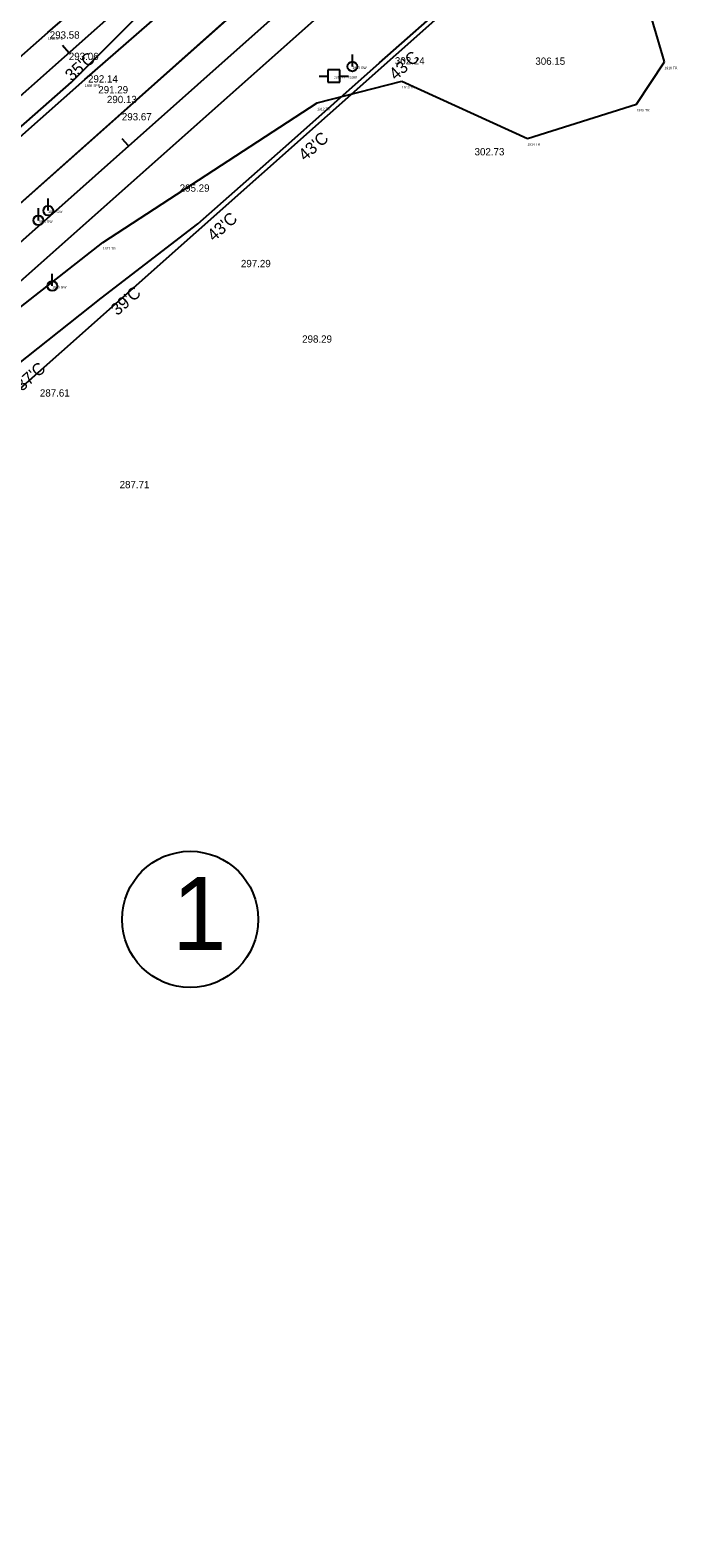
# Model space of a CAD drawing. Extents: x 49683 to 58852, y 49525 to 54803.
# Drawn here: x 55967 to 56233, y 53128 to 53749 of the extents above; entities that cross this region are included whole.
import ezdxf

# ---------------------------------------------------------------- set-up
doc = ezdxf.new("R2010")
doc.units = 0
for name, color, linetype in [('Level 1', 7, 'Continuous'), ('Level 11', 7, 'Continuous'), ('Level 13', 7, 'Continuous'), ('Level 18', 7, 'Continuous'), ('Level 19', 7, 'Continuous'), ('Level 20', 7, 'Continuous'), ('Level 25', 7, 'Continuous'), ('Level 3', 7, 'Continuous'), ('Level 32', 7, 'Continuous'), ('Level 33', 7, 'Continuous'), ('Level 48', 7, 'Continuous'), ('Level 53', 7, 'Continuous'), ('Level 59', 7, 'Continuous'), ('Level 61', 7, 'Continuous'), ('Level 9', 7, 'Continuous')]:
    doc.layers.add(name, color=color, linetype=linetype)

# ---------------------------------------------------------------- blocks, each defined once
blk = doc.blocks.new('GW')
at = {"layer": 'Level 9'}
blk.add_line((0, 0), (0, 5), dxfattribs=at)
blk.add_circle((0, 0), 2, dxfattribs=at)
blk = doc.blocks.new('PP')
at = {"layer": 'Level 9'}
for p, q in [((2.53, 2.45), (-2.47, 2.45)), ((-2.47, 2.45), (-2.47, -2.55)), ((2.53, -2.55), (2.53, 2.45)), ((-5.91, -0.11), (-2.44, -0.11)), ((-2.47, -2.55), (2.53, -2.55)), ((2.45, -0.11), (6.09, -0.11))]:
    blk.add_line(p, q, dxfattribs=at)

msp = doc.modelspace()

# ---------------------------------------------------------------- linework, layer by layer
at = {"layer": 'Level 1'}
for p, q in [((55534.58, 53340.86), (56030.42, 53781.6)), ((55983.03, 53739.48), (55980.37, 53742.47))]:
    msp.add_line(p, q, dxfattribs=at)
at = {"layer": 'Level 11'}
for p, q in [((56228.2, 53735.68), (56218.32, 53769.53)), ((56216.72, 53718.3), (56228.2, 53735.68)), ((56085.22, 53718.79), (56120.13, 53727.76)), ((56120.13, 53727.76), (56171.75, 53704.22)), ((55996.99, 53661.35), (56085.22, 53718.79)), ((56171.75, 53704.22), (56216.72, 53718.3)), ((55939.67, 53616.48), (55996.99, 53661.35))]:
    msp.add_line(p, q, dxfattribs=at)
at = {"layer": 'Level 13'}
msp.add_line((55556.51, 53316.2), (56052.34, 53756.94), dxfattribs=at)
at = {"layer": 'Level 18'}
for p, q in [((56110.9, 53735.37), (56148.42, 53768.43)), ((55984.18, 53727.42), (56019.54, 53762.9)), ((56073.58, 53702.1), (56110.9, 53735.37)), ((55946.66, 53694.37), (55984.18, 53727.42)), ((56036.07, 53669.04), (56073.58, 53702.1)), ((55996.36, 53638.46), (56036.07, 53669.04)), ((55957.14, 53607.32), (55996.36, 53638.46))]:
    msp.add_line(p, q, dxfattribs=at)
at = {"layer": 'Level 19'}
for p, q in [((54181.77, 52078.16), (56150.85, 53828.45)), ((56007.58, 53701.09), (56004.92, 53704.08))]:
    msp.add_line(p, q, dxfattribs=at)
at = {"layer": 'Level 20'}
for p, q in [((55390.95, 53169.04), (56142.88, 53837.41)), ((55400.37, 53145.3), (56158.82, 53819.48))]:
    msp.add_line(p, q, dxfattribs=at)
at = {"layer": 'Level 25'}
msp.add_circle((56032.96, 53382.69), 28.04, dxfattribs=at)
at = {"layer": 'Level 3'}
for p, q in [((55974.42, 53747.84), (56040.5, 53805.43)), ((55989.61, 53728.42), (56055.41, 53785.96)), ((55876.48, 53661.69), (55974.42, 53747.84)), ((55896.99, 53646.4), (55989.61, 53728.42))]:
    msp.add_line(p, q, dxfattribs=at)
at = {"layer": 'Level 33'}
msp.add_line((55925.36, 53567.81), (56180.75, 53794.81), dxfattribs=at)

# ---------------------------------------------------------------- block references
at = {"layer": 'Level 9'}
for name, p in [('GW', (56099.74, 53733.81)), ('PP', (56092.03, 53729.94)), ('GW', (55970.48, 53670.46)), ('GW', (55974.53, 53674.47)), ('GW', (55976.22, 53643.48))]:
    msp.add_blockref(name, p, dxfattribs=at)

# ---------------------------------------------------------------- texts
at = {"layer": 'Level 25'}
msp.add_text('1', height=30, dxfattribs=at).set_placement((56025.54, 53370.15))
at = {"layer": 'Level 32'}
for s, p in [('293.58', (55975.17, 53745.29)), ('293.06', (55983.02, 53736.47)), ('302.24', (56117.22, 53734.64)), ('306.15', (56175.04, 53734.51)), ('292.14', (55990.92, 53727.21)), ('291.29', (55995.14, 53722.74)), ('290.13', (55998.7, 53718.73)), ('293.67', (56004.85, 53711.62)), ('302.73', (56150.02, 53697.21)), ('295.29', (56028.66, 53682.26)), ('297.29', (56053.85, 53651.19)), ('298.29', (56079.05, 53620.12)), ('287.61', (55971.11, 53597.91)), ('287.71', (56003.93, 53560.19))]:
    msp.add_text(s, height=3, dxfattribs=at).set_placement(p)
at = {"layer": 'Level 48'}
for s, rotation, p in [("35'C", 41.63336, (55984.18, 53727.42)), ("43'C", 41.63336, (56117.55, 53727.9)), ("43'C", 41.63336, (56080.23, 53694.63)), ("43'C", 41.63339, (56042.71, 53661.57)), ("39'C", 41.63339, (56003, 53630.98)), ("37'C", 41.63336, (55963.78, 53599.84))]:
    msp.add_text(s, height=5, rotation=rotation, dxfattribs=at).set_placement(p)
at = {"layer": 'Level 53'}
for s, p in [('1885 EPL ', (55974.42, 53744.84)), ('1886 EPR ', (55989.61, 53725.42))]:
    msp.add_text(s, height=1, dxfattribs=at).set_placement(p)
at = {"layer": 'Level 59'}
for s, p in [('1910 GW ', (56099.74, 53732.81)), ('1911 PP 72288 ', (56092.03, 53728.94)), ('1875 GW ', (55974.53, 53673.47)), ('1874 GW ', (55970.48, 53669.46)), ('1876 GW ', (55976.22, 53642.48))]:
    msp.add_text(s, height=1, dxfattribs=at).set_placement(p)
at = {"layer": 'Level 61'}
for s, p in [('1916 TR ', (56228.2, 53732.68)), ('1913 TR ', (56120.13, 53724.76)), ('1912 TR ', (56085.22, 53715.79)), ('1915 TR ', (56216.72, 53715.3)), ('1914 TR ', (56171.75, 53701.22)), ('1877 TR ', (55996.99, 53658.35))]:
    msp.add_text(s, height=1, dxfattribs=at).set_placement(p)

doc.saveas('drawing.dxf')
